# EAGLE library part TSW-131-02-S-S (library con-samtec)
THROUGH-HOLE .025" SQ POST HEADER Source: Samtec TSW.pdf
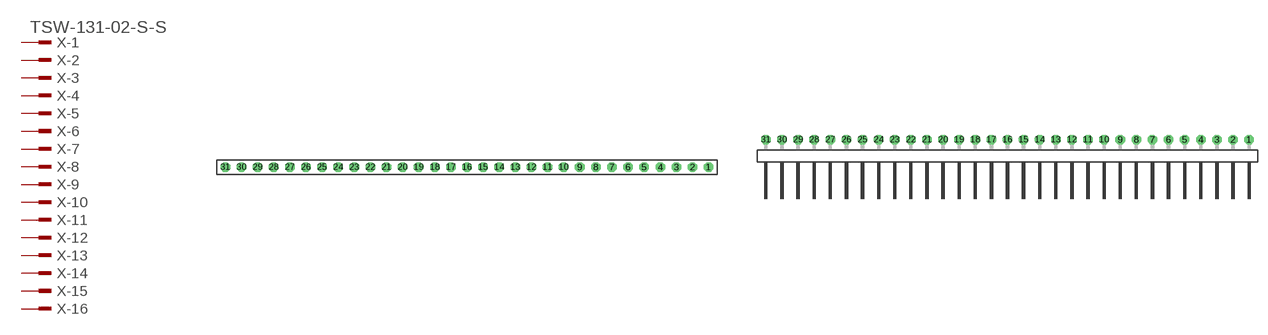
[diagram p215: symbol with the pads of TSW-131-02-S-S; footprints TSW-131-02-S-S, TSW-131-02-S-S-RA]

Designator prefix X; gates -1=MPINV -2=MPIN -3=MPIN -4=MPIN -5=MPIN -6=MPIN -7=MPIN -8=MPIN -9=MPIN -10=MPIN -11=MPIN -12=MPIN -13=MPIN -14=MPIN -15=MPIN -16=MPIN -17=MPIN -18=MPIN -19=MPIN -20=MPIN -21=MPIN -22=MPIN -23=MPIN -24=MPIN -25=MPIN -26=MPIN -27=MPIN -28=MPIN -29=MPIN -30=MPIN -31=MPIN

## TSW-131-02-S-S (OC_FARNELL: unknown; OC_NEWARK: unknown)  [TSW-131-02-S-S]
1  -1:1  pas
2  -2:1  pas
3  -3:1  pas
4  -4:1  pas
5  -5:1  pas
6  -6:1  pas
7  -7:1  pas
8  -8:1  pas
9  -9:1  pas
10  -10:1  pas
11  -11:1  pas
12  -12:1  pas
13  -13:1  pas
14  -14:1  pas
15  -15:1  pas
16  -16:1  pas
17  -17:1  pas
18  -18:1  pas
19  -19:1  pas
20  -20:1  pas
21  -21:1  pas
22  -22:1  pas
23  -23:1  pas
24  -24:1  pas
25  -25:1  pas
26  -26:1  pas
27  -27:1  pas
28  -28:1  pas
29  -29:1  pas
30  -30:1  pas
31  -31:1  pas

## TSW-131-02-S-S-RA (OC_FARNELL: unknown; OC_NEWARK: unknown)  [TSW-131-02-S-S-RA]
Pads as for TSW-131-02-S-S

## Footprint TSW-131-02-S-S (pad centres in mm)
THROUGH-HOLE .025" SQ POST HEADER Source: Samtec TSW.pdf
drill 1 pad 1.5 octagon: 1 38.1,0; 2 35.56,0; 3 33.02,0; 4 30.48,0; 5 27.94,0; 6 25.4,0; 7 22.86,0; 8 20.32,0; 9 17.78,0; 10 15.24,0; 11 12.7,0; 12 10.16,0; 13 7.62,0; 14 5.08,0; 15 2.54,0; 16 0,0; 17 -2.54,0; 18 -5.08,0; 19 -7.62,0; 20 -10.16,0; 21 -12.7,0; 22 -15.24,0; 23 -17.78,0; 24 -20.32,0; 25 -22.86,0; 26 -25.4,0; 27 -27.94,0; 28 -30.48,0; 29 -33.02,0; 30 -35.56,0; 31 -38.1,0

## Footprint TSW-131-02-S-S-RA (pad centres in mm)
THROUGH-HOLE .025" SQ POST HEADER Source: Samtec TSW.pdf
drill 1 pad 1.5 octagon: 1 38.1,1.524; 2 35.56,1.524; 3 33.02,1.524; 4 30.48,1.524; 5 27.94,1.524; 6 25.4,1.524; 7 22.86,1.524; 8 20.32,1.524; 9 17.78,1.524; 10 15.24,1.524; 11 12.7,1.524; 12 10.16,1.524; 13 7.62,1.524; 14 5.08,1.524; 15 2.54,1.524; 16 0,1.524; 17 -2.54,1.524; 18 -5.08,1.524; 19 -7.62,1.524; 20 -10.16,1.524; 21 -12.7,1.524; 22 -15.24,1.524; 23 -17.78,1.524; 24 -20.32,1.524; 25 -22.86,1.524; 26 -25.4,1.524; 27 -27.94,1.524; 28 -30.48,1.524; 29 -33.02,1.524; 30 -35.56,1.524; 31 -38.1,1.524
